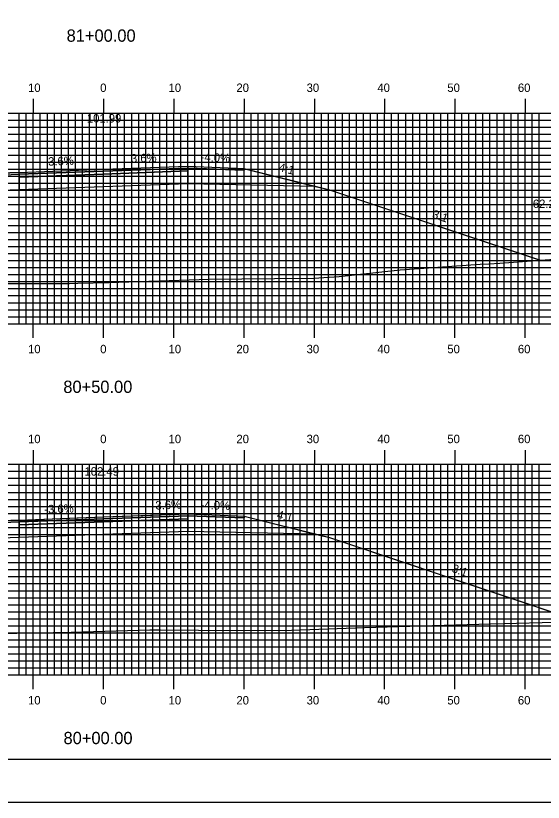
# Model space of a CAD drawing. Extents: x 1762578 to 1762921, y 442591 to 442811.
# Drawn here: x 1762731.3 to 1762806.4, y 442590.5 to 442702.5 of the extents above; entities that cross this region are included whole.
import ezdxf

# ---------------------------------------------------------------- set-up
doc = ezdxf.new("R2010")
doc.units = 0
for name, color, linetype in [('ANNOTATION', 7, 'Continuous'), ('BORDER', 7, 'Continuous'), ('D_Roadway_Centerline', 7, 'Continuous'), ('D_Roadway_Centerline_Text', 7, 'Continuous'), ('D_Roadway_Edge_Shoulder', 7, 'Continuous'), ('D_Roadway_Edge_TW', 7, 'Continuous'), ('D_Roadway_Pavement', 7, 'Continuous'), ('D_Roadway_SlopeLines', 7, 'Continuous'), ('D_Roadway_SubGrade', 7, 'Continuous'), ('D_Text_Standard', 7, 'Continuous'), ('H_V ANNOTATION', 7, 'Continuous'), ('MAJOR', 7, 'Continuous'), ('MINOR', 7, 'Continuous'), ('PLOT BOUNDARY', 7, 'Continuous'), ('S_Roadway_Centerline', 7, 'Continuous')]:
    doc.layers.add(name, color=color, linetype=linetype)

msp = doc.modelspace()

# ---------------------------------------------------------------- linework, layer by layer
at = {"layer": 'BORDER'}
msp.add_lwpolyline([(1762594.18, 442596.67), (1762914.18, 442596.67), (1762914.18, 442806.67), (1762594.18, 442806.67)], close=True, dxfattribs=at)
at = {"layer": 'D_Roadway_Centerline'}
for points in [[(1762676.09, 442665.01), (1762676.09, 442665.01), (1762711.78, 442676.9), (1762712, 442676.96), (1762712.25, 442677.02), (1762712.25, 442677.02), (1762716.68, 442678.13), (1762723.78, 442679.9), (1762723.78, 442679.9), (1762731.78, 442680.22), (1762739.05, 442680.48), (1762743.78, 442680.66), (1762743.78, 442680.66), (1762755.78, 442681.09), (1762763.78, 442680.77), (1762764.26, 442680.65), (1762773.95, 442678.22), (1762775.78, 442677.77), (1762805.93, 442667.72), (1762805.95, 442667.71)], [(1762668.07, 442614.67), (1762668.08, 442614.67), (1762705.54, 442627.15), (1762706.12, 442627.3), (1762706.12, 442627.3), (1762717.54, 442630.15), (1762717.54, 442630.15), (1762726.98, 442630.53), (1762731.78, 442630.72), (1762731.78, 442630.72), (1762738.78, 442630.98), (1762743.78, 442631.16), (1762743.78, 442631.16), (1762750.76, 442631.41), (1762755.78, 442631.59), (1762755.78, 442631.59), (1762763.78, 442631.27), (1762773.95, 442628.72), (1762773.95, 442628.72), (1762774.91, 442628.48), (1762775.78, 442628.27), (1762802.49, 442619.36), (1762811.53, 442616.35)]]:
    msp.add_lwpolyline(points, dxfattribs=at)
at = {"layer": 'D_Roadway_Edge_Shoulder'}
for points in [[(1762755.78, 442681.09), (1762763.78, 442680.77), (1762763.78, 442680.52), (1762755.78, 442680.84)], [(1762731.78, 442680.22), (1762723.78, 442679.9), (1762723.78, 442679.65), (1762731.78, 442679.97)], [(1762755.78, 442631.59), (1762763.78, 442631.27), (1762763.78, 442631.02), (1762755.78, 442631.34)], [(1762731.78, 442630.72), (1762717.54, 442630.15), (1762717.54, 442629.9), (1762731.78, 442630.47)]]:
    msp.add_lwpolyline(points, close=True, dxfattribs=at)
at = {"layer": 'D_Roadway_Edge_TW'}
for points in [[(1762731.78, 442679.97), (1762731.78, 442680.22), (1762743.78, 442680.66), (1762755.78, 442681.09), (1762755.78, 442680.84), (1762743.78, 442680.41)], [(1762755.78, 442681.09), (1762755.78, 442681.09), (1762755.78, 442680.84), (1762755.78, 442680.84)], [(1762731.78, 442630.47), (1762731.78, 442630.72), (1762743.78, 442631.16), (1762755.78, 442631.59), (1762755.78, 442631.34), (1762743.78, 442630.91)], [(1762755.78, 442631.59), (1762755.78, 442631.59), (1762755.78, 442631.34), (1762755.78, 442631.34)]]:
    msp.add_lwpolyline(points, close=True, dxfattribs=at)
at = {"layer": 'D_Roadway_Pavement'}
for points in [[(1762731.78, 442679.56), (1762731.78, 442679.97), (1762743.78, 442680.41), (1762755.78, 442680.84), (1762755.78, 442680.42), (1762743.78, 442679.99)], [(1762755.78, 442680.84), (1762755.78, 442680.84), (1762755.78, 442680.42), (1762755.78, 442680.42)], [(1762731.78, 442630.06), (1762731.78, 442630.47), (1762743.78, 442630.91), (1762755.78, 442631.34), (1762755.78, 442630.92), (1762743.78, 442630.49)], [(1762755.78, 442631.34), (1762755.78, 442631.34), (1762755.78, 442630.92), (1762755.78, 442630.92)]]:
    msp.add_lwpolyline(points, close=True, dxfattribs=at)
for points in [[(1762755.78, 442680.84), (1762755.78, 442680.42)], [(1762755.78, 442680.84), (1762755.78, 442680.42)], [(1762755.78, 442680.84), (1762755.78, 442680.42)], [(1762755.78, 442631.34), (1762755.78, 442630.92)], [(1762755.78, 442631.34), (1762755.78, 442630.92)], [(1762755.78, 442631.34), (1762755.78, 442630.92)]]:
    msp.add_lwpolyline(points, dxfattribs=at)
at = {"layer": 'D_Roadway_SlopeLines'}
for points in [[(1762763.78, 442680.77), (1762775.78, 442677.77), (1762805.95, 442667.71)], [(1762763.78, 442631.27), (1762775.78, 442628.27), (1762811.53, 442616.35)]]:
    msp.add_lwpolyline(points, dxfattribs=at)
at = {"layer": 'D_Roadway_SubGrade'}
for points in [[(1762755.78, 442680.42), (1762755.78, 442680.84), (1762763.78, 442680.52), (1762763.78, 442680.77), (1762773.95, 442678.22), (1762755.78, 442678.59)], [(1762723.78, 442679.65), (1762731.78, 442679.97), (1762731.78, 442679.56), (1762731.78, 442677.72), (1762712.25, 442677.02), (1762723.78, 442679.9)], [(1762731.78, 442677.72), (1762731.78, 442679.56), (1762743.78, 442679.99), (1762755.78, 442680.42), (1762755.78, 442678.59), (1762743.78, 442678.16)], [(1762755.78, 442680.42), (1762755.78, 442680.42), (1762755.78, 442678.59), (1762755.78, 442678.59)], [(1762717.54, 442629.9), (1762731.78, 442630.47), (1762731.78, 442630.06), (1762731.78, 442628.22), (1762706.12, 442627.3), (1762717.54, 442630.15)], [(1762731.78, 442628.22), (1762731.78, 442630.06), (1762743.78, 442630.49), (1762755.78, 442630.92), (1762755.78, 442629.09), (1762743.78, 442628.66)], [(1762755.78, 442630.92), (1762755.78, 442631.34), (1762763.78, 442631.02), (1762763.78, 442631.27), (1762773.95, 442628.72), (1762755.78, 442629.09)], [(1762755.78, 442630.92), (1762755.78, 442630.92), (1762755.78, 442629.09), (1762755.78, 442629.09)]]:
    msp.add_lwpolyline(points, close=True, dxfattribs=at)
at = {"layer": 'MAJOR'}
for p, q in [((1762733.78, 442690.67), (1762733.78, 442688.67)), ((1762743.78, 442690.67), (1762743.78, 442688.67)), ((1762753.78, 442690.67), (1762753.78, 442688.67)), ((1762763.78, 442690.67), (1762763.78, 442688.67)), ((1762773.78, 442690.67), (1762773.78, 442688.67)), ((1762783.78, 442690.67), (1762783.78, 442688.67)), ((1762793.78, 442690.67), (1762793.78, 442688.67)), ((1762803.78, 442690.67), (1762803.78, 442688.67)), ((1762603.78, 442688.67), (1762883.78, 442688.67)), ((1762603.78, 442688.67), (1762883.78, 442688.67)), ((1762733.78, 442658.67), (1762733.78, 442688.67)), ((1762743.78, 442658.67), (1762743.78, 442688.67)), ((1762753.78, 442658.67), (1762753.78, 442688.67)), ((1762763.78, 442658.67), (1762763.78, 442688.67)), ((1762773.78, 442658.67), (1762773.78, 442688.67)), ((1762783.78, 442658.67), (1762783.78, 442688.67)), ((1762793.78, 442658.67), (1762793.78, 442688.67)), ((1762803.78, 442658.67), (1762803.78, 442688.67)), ((1762603.78, 442683.67), (1762883.78, 442683.67)), ((1762603.78, 442678.67), (1762883.78, 442678.67)), ((1762603.78, 442673.67), (1762883.78, 442673.67)), ((1762603.78, 442668.67), (1762883.78, 442668.67)), ((1762603.78, 442663.67), (1762883.78, 442663.67)), ((1762603.78, 442658.67), (1762883.78, 442658.67)), ((1762603.78, 442658.67), (1762883.78, 442658.67)), ((1762733.78, 442656.66), (1762733.78, 442658.67)), ((1762743.78, 442656.66), (1762743.78, 442658.67)), ((1762753.78, 442656.66), (1762753.78, 442658.67)), ((1762763.78, 442656.66), (1762763.78, 442658.67)), ((1762773.78, 442656.66), (1762773.78, 442658.67)), ((1762783.78, 442656.66), (1762783.78, 442658.67)), ((1762793.78, 442656.66), (1762793.78, 442658.67)), ((1762803.78, 442656.66), (1762803.78, 442658.67)), ((1762733.78, 442640.67), (1762733.78, 442638.67)), ((1762743.78, 442640.67), (1762743.78, 442638.67)), ((1762753.78, 442640.67), (1762753.78, 442638.67)), ((1762763.78, 442640.67), (1762763.78, 442638.67)), ((1762773.78, 442640.67), (1762773.78, 442638.67)), ((1762783.78, 442640.67), (1762783.78, 442638.67)), ((1762793.78, 442640.67), (1762793.78, 442638.67)), ((1762803.78, 442640.67), (1762803.78, 442638.67)), ((1762603.78, 442638.67), (1762883.78, 442638.67)), ((1762603.78, 442638.67), (1762883.78, 442638.67)), ((1762733.78, 442608.67), (1762733.78, 442638.67)), ((1762743.78, 442608.67), (1762743.78, 442638.67)), ((1762753.78, 442608.67), (1762753.78, 442638.67)), ((1762763.78, 442608.67), (1762763.78, 442638.67)), ((1762773.78, 442608.67), (1762773.78, 442638.67)), ((1762783.78, 442608.67), (1762783.78, 442638.67)), ((1762793.78, 442608.67), (1762793.78, 442638.67)), ((1762803.78, 442608.67), (1762803.78, 442638.67)), ((1762603.78, 442633.67), (1762883.78, 442633.67)), ((1762603.78, 442628.67), (1762883.78, 442628.67)), ((1762603.78, 442623.67), (1762883.78, 442623.67)), ((1762603.78, 442618.67), (1762883.78, 442618.67)), ((1762603.78, 442613.67), (1762883.78, 442613.67)), ((1762603.78, 442608.67), (1762883.78, 442608.67)), ((1762603.78, 442608.67), (1762883.78, 442608.67)), ((1762733.78, 442606.66), (1762733.78, 442608.67)), ((1762743.78, 442606.66), (1762743.78, 442608.67)), ((1762753.78, 442606.66), (1762753.78, 442608.67)), ((1762763.78, 442606.66), (1762763.78, 442608.67)), ((1762773.78, 442606.66), (1762773.78, 442608.67)), ((1762783.78, 442606.66), (1762783.78, 442608.67)), ((1762793.78, 442606.66), (1762793.78, 442608.67)), ((1762803.78, 442606.66), (1762803.78, 442608.67))]:
    msp.add_line(p, q, dxfattribs=at)
at = {"layer": 'MINOR'}
for p, q in [((1762731.78, 442658.67), (1762731.78, 442688.67)), ((1762732.78, 442658.67), (1762732.78, 442688.67)), ((1762734.78, 442658.67), (1762734.78, 442688.67)), ((1762735.78, 442658.67), (1762735.78, 442688.67)), ((1762736.78, 442658.67), (1762736.78, 442688.67)), ((1762737.78, 442658.67), (1762737.78, 442688.67)), ((1762738.78, 442658.67), (1762738.78, 442688.67)), ((1762739.78, 442658.67), (1762739.78, 442688.67)), ((1762740.78, 442658.67), (1762740.78, 442688.67)), ((1762741.78, 442658.67), (1762741.78, 442688.67)), ((1762742.78, 442658.67), (1762742.78, 442688.67)), ((1762744.78, 442658.67), (1762744.78, 442688.67)), ((1762745.78, 442658.67), (1762745.78, 442688.67)), ((1762746.78, 442658.67), (1762746.78, 442688.67)), ((1762747.78, 442658.67), (1762747.78, 442688.67)), ((1762748.78, 442658.67), (1762748.78, 442688.67)), ((1762749.78, 442658.67), (1762749.78, 442688.67)), ((1762750.78, 442658.67), (1762750.78, 442688.67)), ((1762751.78, 442658.67), (1762751.78, 442688.67)), ((1762752.78, 442658.67), (1762752.78, 442688.67)), ((1762754.78, 442658.67), (1762754.78, 442688.67)), ((1762755.78, 442658.67), (1762755.78, 442688.67)), ((1762756.78, 442658.67), (1762756.78, 442688.67)), ((1762757.78, 442658.67), (1762757.78, 442688.67)), ((1762758.78, 442658.67), (1762758.78, 442688.67)), ((1762759.78, 442658.67), (1762759.78, 442688.67)), ((1762760.78, 442658.67), (1762760.78, 442688.67)), ((1762761.78, 442658.67), (1762761.78, 442688.67)), ((1762762.78, 442658.67), (1762762.78, 442688.67)), ((1762764.78, 442658.67), (1762764.78, 442688.67)), ((1762765.78, 442658.67), (1762765.78, 442688.67)), ((1762766.78, 442658.67), (1762766.78, 442688.67)), ((1762767.78, 442658.67), (1762767.78, 442688.67)), ((1762768.78, 442658.67), (1762768.78, 442688.67)), ((1762769.78, 442658.67), (1762769.78, 442688.67)), ((1762770.78, 442658.67), (1762770.78, 442688.67)), ((1762771.78, 442658.67), (1762771.78, 442688.67)), ((1762772.78, 442658.67), (1762772.78, 442688.67)), ((1762774.78, 442658.67), (1762774.78, 442688.67)), ((1762775.78, 442658.67), (1762775.78, 442688.67)), ((1762776.78, 442658.67), (1762776.78, 442688.67)), ((1762777.78, 442658.67), (1762777.78, 442688.67)), ((1762778.78, 442658.67), (1762778.78, 442688.67)), ((1762779.78, 442658.67), (1762779.78, 442688.67)), ((1762780.78, 442658.67), (1762780.78, 442688.67)), ((1762781.78, 442658.67), (1762781.78, 442688.67)), ((1762782.78, 442658.67), (1762782.78, 442688.67)), ((1762784.78, 442658.67), (1762784.78, 442688.67)), ((1762785.78, 442658.67), (1762785.78, 442688.67)), ((1762786.78, 442658.67), (1762786.78, 442688.67)), ((1762787.78, 442658.67), (1762787.78, 442688.67)), ((1762788.78, 442658.67), (1762788.78, 442688.67)), ((1762789.78, 442658.67), (1762789.78, 442688.67)), ((1762790.78, 442658.67), (1762790.78, 442688.67)), ((1762791.78, 442658.67), (1762791.78, 442688.67)), ((1762792.78, 442658.67), (1762792.78, 442688.67)), ((1762794.78, 442658.67), (1762794.78, 442688.67)), ((1762795.78, 442658.67), (1762795.78, 442688.67)), ((1762796.78, 442658.67), (1762796.78, 442688.67)), ((1762797.78, 442658.67), (1762797.78, 442688.67)), ((1762798.78, 442658.67), (1762798.78, 442688.67)), ((1762799.78, 442658.67), (1762799.78, 442688.67)), ((1762800.78, 442658.67), (1762800.78, 442688.67)), ((1762801.78, 442658.67), (1762801.78, 442688.67)), ((1762802.78, 442658.67), (1762802.78, 442688.67)), ((1762804.78, 442658.67), (1762804.78, 442688.67)), ((1762805.78, 442658.67), (1762805.78, 442688.67)), ((1762603.78, 442687.67), (1762883.78, 442687.67)), ((1762603.78, 442686.67), (1762883.78, 442686.67)), ((1762603.78, 442685.67), (1762883.78, 442685.67)), ((1762603.78, 442684.67), (1762883.78, 442684.67)), ((1762603.78, 442682.67), (1762883.78, 442682.67)), ((1762603.78, 442681.67), (1762883.78, 442681.67)), ((1762603.78, 442680.67), (1762883.78, 442680.67)), ((1762603.78, 442679.67), (1762883.78, 442679.67)), ((1762603.78, 442677.67), (1762883.78, 442677.67)), ((1762603.78, 442676.67), (1762883.78, 442676.67)), ((1762603.78, 442675.67), (1762883.78, 442675.67)), ((1762603.78, 442674.67), (1762883.78, 442674.67)), ((1762603.78, 442672.67), (1762883.78, 442672.67)), ((1762603.78, 442671.67), (1762883.78, 442671.67)), ((1762603.78, 442670.67), (1762883.78, 442670.67)), ((1762603.78, 442669.67), (1762883.78, 442669.67)), ((1762603.78, 442667.67), (1762883.78, 442667.67)), ((1762603.78, 442666.67), (1762883.78, 442666.67)), ((1762603.78, 442665.67), (1762883.78, 442665.67)), ((1762603.78, 442664.67), (1762883.78, 442664.67)), ((1762603.78, 442662.67), (1762883.78, 442662.67)), ((1762603.78, 442661.67), (1762883.78, 442661.67)), ((1762603.78, 442660.67), (1762883.78, 442660.67)), ((1762603.78, 442659.67), (1762883.78, 442659.67)), ((1762731.78, 442608.67), (1762731.78, 442638.67)), ((1762732.78, 442608.67), (1762732.78, 442638.67)), ((1762734.78, 442608.67), (1762734.78, 442638.67)), ((1762735.78, 442608.67), (1762735.78, 442638.67)), ((1762736.78, 442608.67), (1762736.78, 442638.67)), ((1762737.78, 442608.67), (1762737.78, 442638.67)), ((1762738.78, 442608.67), (1762738.78, 442638.67)), ((1762739.78, 442608.67), (1762739.78, 442638.67)), ((1762740.78, 442608.67), (1762740.78, 442638.67)), ((1762741.78, 442608.67), (1762741.78, 442638.67)), ((1762742.78, 442608.67), (1762742.78, 442638.67)), ((1762744.78, 442608.67), (1762744.78, 442638.67)), ((1762745.78, 442608.67), (1762745.78, 442638.67)), ((1762746.78, 442608.67), (1762746.78, 442638.67)), ((1762747.78, 442608.67), (1762747.78, 442638.67)), ((1762748.78, 442608.67), (1762748.78, 442638.67)), ((1762749.78, 442608.67), (1762749.78, 442638.67)), ((1762750.78, 442608.67), (1762750.78, 442638.67)), ((1762751.78, 442608.67), (1762751.78, 442638.67)), ((1762752.78, 442608.67), (1762752.78, 442638.67)), ((1762754.78, 442608.67), (1762754.78, 442638.67)), ((1762755.78, 442608.67), (1762755.78, 442638.67)), ((1762756.78, 442608.67), (1762756.78, 442638.67)), ((1762757.78, 442608.67), (1762757.78, 442638.67)), ((1762758.78, 442608.67), (1762758.78, 442638.67)), ((1762759.78, 442608.67), (1762759.78, 442638.67)), ((1762760.78, 442608.67), (1762760.78, 442638.67)), ((1762761.78, 442608.67), (1762761.78, 442638.67)), ((1762762.78, 442608.67), (1762762.78, 442638.67)), ((1762764.78, 442608.67), (1762764.78, 442638.67)), ((1762765.78, 442608.67), (1762765.78, 442638.67)), ((1762766.78, 442608.67), (1762766.78, 442638.67)), ((1762767.78, 442608.67), (1762767.78, 442638.67)), ((1762768.78, 442608.67), (1762768.78, 442638.67)), ((1762769.78, 442608.67), (1762769.78, 442638.67)), ((1762770.78, 442608.67), (1762770.78, 442638.67)), ((1762771.78, 442608.67), (1762771.78, 442638.67)), ((1762772.78, 442608.67), (1762772.78, 442638.67)), ((1762774.78, 442608.67), (1762774.78, 442638.67)), ((1762775.78, 442608.67), (1762775.78, 442638.67)), ((1762776.78, 442608.67), (1762776.78, 442638.67)), ((1762777.78, 442608.67), (1762777.78, 442638.67)), ((1762778.78, 442608.67), (1762778.78, 442638.67)), ((1762779.78, 442608.67), (1762779.78, 442638.67)), ((1762780.78, 442608.67), (1762780.78, 442638.67)), ((1762781.78, 442608.67), (1762781.78, 442638.67)), ((1762782.78, 442608.67), (1762782.78, 442638.67)), ((1762784.78, 442608.67), (1762784.78, 442638.67)), ((1762785.78, 442608.67), (1762785.78, 442638.67)), ((1762786.78, 442608.67), (1762786.78, 442638.67)), ((1762787.78, 442608.67), (1762787.78, 442638.67)), ((1762788.78, 442608.67), (1762788.78, 442638.67)), ((1762789.78, 442608.67), (1762789.78, 442638.67)), ((1762790.78, 442608.67), (1762790.78, 442638.67)), ((1762791.78, 442608.67), (1762791.78, 442638.67)), ((1762792.78, 442608.67), (1762792.78, 442638.67)), ((1762794.78, 442608.67), (1762794.78, 442638.67)), ((1762795.78, 442608.67), (1762795.78, 442638.67)), ((1762796.78, 442608.67), (1762796.78, 442638.67)), ((1762797.78, 442608.67), (1762797.78, 442638.67)), ((1762798.78, 442608.67), (1762798.78, 442638.67)), ((1762799.78, 442608.67), (1762799.78, 442638.67)), ((1762800.78, 442608.67), (1762800.78, 442638.67)), ((1762801.78, 442608.67), (1762801.78, 442638.67)), ((1762802.78, 442608.67), (1762802.78, 442638.67)), ((1762804.78, 442608.67), (1762804.78, 442638.67)), ((1762805.78, 442608.67), (1762805.78, 442638.67)), ((1762603.78, 442637.67), (1762883.78, 442637.67)), ((1762603.78, 442636.67), (1762883.78, 442636.67)), ((1762603.78, 442635.67), (1762883.78, 442635.67)), ((1762603.78, 442634.67), (1762883.78, 442634.67)), ((1762603.78, 442632.67), (1762883.78, 442632.67)), ((1762603.78, 442631.67), (1762883.78, 442631.67)), ((1762603.78, 442630.67), (1762883.78, 442630.67)), ((1762603.78, 442629.67), (1762883.78, 442629.67)), ((1762603.78, 442627.67), (1762883.78, 442627.67)), ((1762603.78, 442626.67), (1762883.78, 442626.67)), ((1762603.78, 442625.67), (1762883.78, 442625.67)), ((1762603.78, 442624.67), (1762883.78, 442624.67)), ((1762603.78, 442622.67), (1762883.78, 442622.67)), ((1762603.78, 442621.67), (1762883.78, 442621.67)), ((1762603.78, 442620.67), (1762883.78, 442620.67)), ((1762603.78, 442619.67), (1762883.78, 442619.67)), ((1762603.78, 442617.67), (1762883.78, 442617.67)), ((1762603.78, 442616.67), (1762883.78, 442616.67)), ((1762603.78, 442615.67), (1762883.78, 442615.67)), ((1762603.78, 442614.67), (1762883.78, 442614.67)), ((1762603.78, 442612.67), (1762883.78, 442612.67)), ((1762603.78, 442611.67), (1762883.78, 442611.67)), ((1762603.78, 442610.67), (1762883.78, 442610.67)), ((1762603.78, 442609.67), (1762883.78, 442609.67))]:
    msp.add_line(p, q, dxfattribs=at)
at = {"layer": 'PLOT BOUNDARY'}
msp.add_lwpolyline([(1762577.99, 442590.55), (1762917.99, 442590.55), (1762917.99, 442810.55), (1762577.99, 442810.55)], close=True, dxfattribs=at)
at = {"layer": 'S_Roadway_Centerline'}
for points in [[(1762663.21, 442665.11), (1762674.57, 442665.04), (1762679.13, 442664.93), (1762693.88, 442664.49), (1762700.7, 442664.23), (1762702.15, 442664.25), (1762721.7, 442664.39), (1762737.26, 442664.39), (1762738.93, 442664.41), (1762740.1, 442664.43), (1762744.54, 442664.53), (1762758.8, 442665.01), (1762768.12, 442665.12), (1762773.73, 442665.16), (1762777.32, 442665.4), (1762785.99, 442666.35), (1762797.39, 442667.15), (1762798.62, 442667.21), (1762800.16, 442667.29), (1762816.36, 442668.47)], [(1762657.2, 442614.76), (1762673.81, 442614.61), (1762690.09, 442614.26), (1762693.66, 442614.2), (1762701.23, 442614.34), (1762713.81, 442614.72), (1762716.03, 442614.67), (1762719.97, 442614.59), (1762727.01, 442614.49), (1762731.42, 442614.61), (1762739.16, 442614.78), (1762750.36, 442615.08), (1762751.9, 442615.09), (1762762.68, 442614.98), (1762770.55, 442615.05), (1762780.92, 442615.43), (1762790.62, 442615.71), (1762798.83, 442615.96), (1762809.91, 442616.24)]]:
    msp.add_lwpolyline(points, dxfattribs=at)

# ---------------------------------------------------------------- texts
at = {"layer": 'ANNOTATION'}
for s, rotation, p in [('-4.0%', 357.7093, (1762757.57, 442681.82)), ('-3.6%', 2.0617, (1762735.37, 442681.15)), ('3.6%', 2.0618, (1762747.69, 442681.6)), ('4:1', 345.9616, (1762768.61, 442680.42)), ('3:1', 341.5646, (1762790.46, 442673.78)), ('-3.6%', 2.0618, (1762735.36, 442631.65)), ('3.6%', 2.0617, (1762751.18, 442632.22)), ('-4.0%', 357.7094, (1762757.57, 442632.32)), ('4:1', 345.9603, (1762768.37, 442630.98)), ('3:1', 341.5639, (1762793.26, 442623.35))]:
    msp.add_text(s, height=1.2, rotation=rotation, dxfattribs=at).set_placement(p)
at = {"layer": 'D_Roadway_Centerline'}
for s, p in [('C', (1762743.77, 442680.66)), ('L', (1762743.78, 442680.65)), ('C', (1762743.77, 442631.16)), ('L', (1762743.78, 442631.15))]:
    msp.add_text(s, height=0.0146, dxfattribs=at).set_placement(p)
at = {"layer": 'D_Roadway_Centerline_Text'}
for s, p in [('101.99', (1762741.4, 442687.32)), ('102.49', (1762741.06, 442637.05))]:
    msp.add_text(s, height=1.2, dxfattribs=at).set_placement(p)
at = {"layer": 'D_Text_Standard'}
msp.add_text("62.2'", height=1.2, dxfattribs=at).set_placement((1762804.88, 442675.15))
at = {"layer": 'H_V ANNOTATION'}
for s, height, p in [('81+00.00', 1.75, (1762738.52, 442698.82)), ('10', 1.2, (1762733.03, 442691.67)), ('0', 1.2, (1762743.3, 442691.67)), ('10', 1.2, (1762753.03, 442691.67)), ('20', 1.2, (1762762.69, 442691.67)), ('30', 1.2, (1762772.68, 442691.67)), ('40', 1.2, (1762782.75, 442691.67)), ('50', 1.2, (1762792.71, 442691.67)), ('60', 1.2, (1762802.75, 442691.67)), ('10', 1.2, (1762733.03, 442654.47)), ('0', 1.2, (1762743.3, 442654.47)), ('10', 1.2, (1762753.03, 442654.47)), ('20', 1.2, (1762762.69, 442654.47)), ('30', 1.2, (1762772.68, 442654.47)), ('40', 1.2, (1762782.75, 442654.47)), ('50', 1.2, (1762792.71, 442654.47)), ('60', 1.2, (1762802.75, 442654.47)), ('80+50.00', 1.75, (1762738.05, 442648.82)), ('10', 1.2, (1762733.03, 442641.67)), ('0', 1.2, (1762743.3, 442641.67)), ('10', 1.2, (1762753.03, 442641.67)), ('20', 1.2, (1762762.69, 442641.67)), ('30', 1.2, (1762772.68, 442641.67)), ('40', 1.2, (1762782.75, 442641.67)), ('50', 1.2, (1762792.71, 442641.67)), ('60', 1.2, (1762802.75, 442641.67)), ('10', 1.2, (1762733.03, 442604.47)), ('0', 1.2, (1762743.3, 442604.47)), ('10', 1.2, (1762753.03, 442604.47)), ('20', 1.2, (1762762.69, 442604.47)), ('30', 1.2, (1762772.68, 442604.47)), ('40', 1.2, (1762782.75, 442604.47)), ('50', 1.2, (1762792.71, 442604.47)), ('60', 1.2, (1762802.75, 442604.47)), ('80+00.00', 1.75, (1762738.08, 442598.82))]:
    msp.add_text(s, height=height, dxfattribs=at).set_placement(p)

doc.saveas('drawing.dxf')
